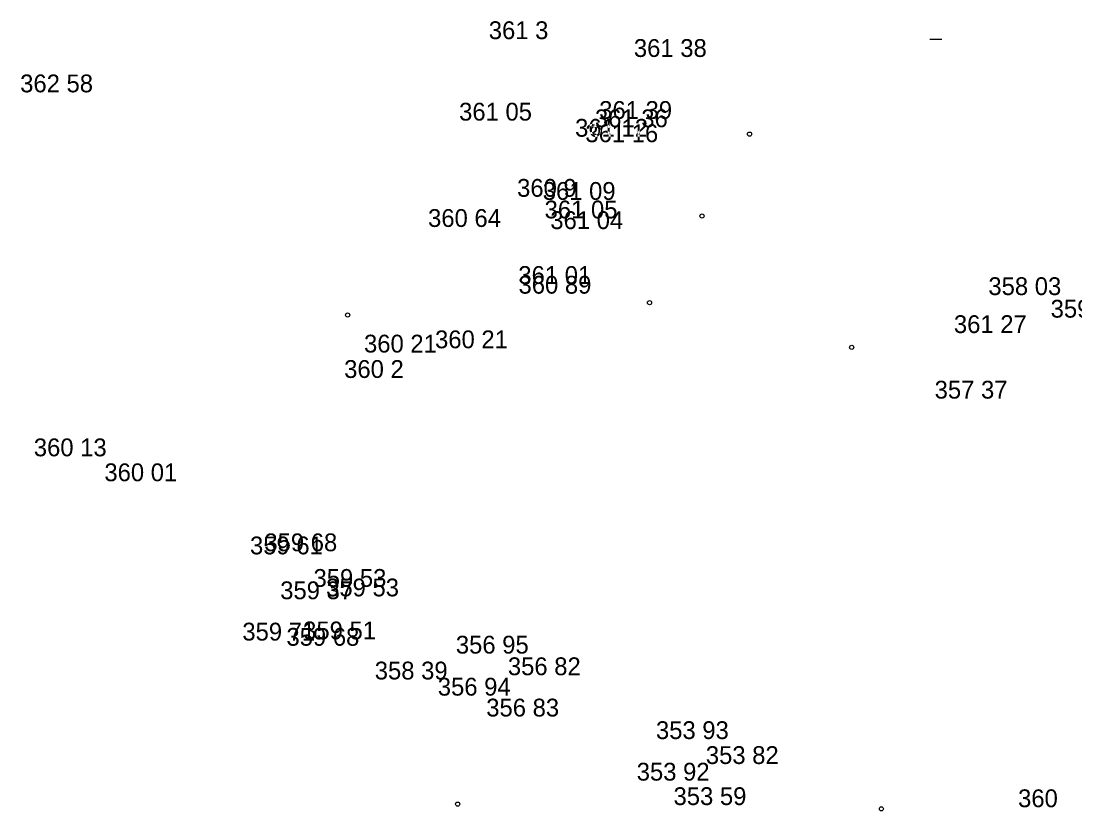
# Model space of a CAD drawing. Extents: x -688316 to -688024, y -973785 to -973591.
# Drawn here: x -688235.96 to -688191.59, y -973732.89 to -973699.62 of the extents above; entities that cross this region are included whole.
import ezdxf

# ---------------------------------------------------------------- set-up
doc = ezdxf.new("R2010")
doc.units = 0
doc.layers.add('Vrstva 3', color=7, linetype='Continuous')
doc.layers.add('Vrstva 58', color=7, linetype='Continuous')

# ---------------------------------------------------------------- blocks, each defined once
blk = doc.blocks.new('B_NESP')
at = {"layer": 'Vrstva 58'}
blk.add_circle((0, 0), 0.875, dxfattribs=at)
blk = doc.blocks.new('B_SPAL')
at = {"layer": 'Vrstva 58'}
blk.add_line((-2.5, 0), (2.5, 0), dxfattribs=at)

msp = doc.modelspace()

# ---------------------------------------------------------------- block references
at = {"layer": 'Vrstva 58', "xscale": 0.1, "yscale": 0.10000000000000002}
for name, p in [('B_SPAL', (-688197.45, -973700.38)), ('B_SPAL', (-688197.45, -973700.38)), ('B_SPAL', (-688197.45, -973700.38)), ('B_SPAL', (-688197.45, -973700.38)), ('B_NESP', (-688205.29, -973704.38)), ('B_NESP', (-688205.29, -973704.38)), ('B_NESP', (-688205.29, -973704.38)), ('B_NESP', (-688205.29, -973704.38)), ('B_NESP', (-688207.29, -973707.83)), ('B_NESP', (-688207.29, -973707.83)), ('B_NESP', (-688207.29, -973707.83)), ('B_NESP', (-688207.29, -973707.83)), ('B_NESP', (-688209.5, -973711.48)), ('B_NESP', (-688209.5, -973711.48)), ('B_NESP', (-688209.5, -973711.48)), ('B_NESP', (-688209.5, -973711.48)), ('B_NESP', (-688222.21, -973712)), ('B_NESP', (-688222.21, -973712)), ('B_NESP', (-688222.21, -973712)), ('B_NESP', (-688222.21, -973712)), ('B_NESP', (-688200.99, -973713.36)), ('B_NESP', (-688200.99, -973713.36)), ('B_NESP', (-688200.99, -973713.36)), ('B_NESP', (-688200.99, -973713.36)), ('B_NESP', (-688217.58, -973732.6)), ('B_NESP', (-688217.58, -973732.6)), ('B_NESP', (-688199.74, -973732.8)), ('B_NESP', (-688199.74, -973732.8))]:
    msp.add_blockref(name, p, dxfattribs=at)

# ---------------------------------------------------------------- texts
at = {"layer": 'Vrstva 3'}
for s, p in [('361 3  ', (-688216.269, -973700.38)), ('361 3  ', (-688216.269, -973700.38)), ('361 3  ', (-688216.269, -973700.38)), ('361 3  ', (-688216.269, -973700.38)), ('361 3  ', (-688216.269, -973700.38)), ('361 3  ', (-688216.269, -973700.38)), ('361 3  ', (-688216.269, -973700.38)), ('361 38 ', (-688210.16, -973701.13)), ('361 38 ', (-688210.16, -973701.13)), ('361 38 ', (-688210.16, -973701.13)), ('361 38 ', (-688210.16, -973701.13)), ('361 38 ', (-688210.16, -973701.13)), ('361 38 ', (-688210.16, -973701.13)), ('361 38 ', (-688210.16, -973701.13)), ('362 58 ', (-688235.996, -973702.62)), ('362 58 ', (-688235.996, -973702.62)), ('362 58 ', (-688235.996, -973702.62)), ('362 58 ', (-688235.996, -973702.62)), ('362 58 ', (-688235.996, -973702.62)), ('362 58 ', (-688235.996, -973702.62)), ('362 58 ', (-688235.996, -973702.62)), ('361 05 ', (-688217.518, -973703.81)), ('361 05 ', (-688217.518, -973703.81)), ('361 05 ', (-688217.518, -973703.81)), ('361 05 ', (-688217.518, -973703.81)), ('361 05 ', (-688217.518, -973703.81)), ('361 05 ', (-688217.518, -973703.81)), ('361 05 ', (-688217.518, -973703.81)), ('361 39 ', (-688211.62, -973703.74)), ('361 39 ', (-688211.62, -973703.74)), ('361 39 ', (-688211.62, -973703.74)), ('361 39 ', (-688211.62, -973703.74)), ('361 39 ', (-688211.62, -973703.74)), ('361 39 ', (-688211.62, -973703.74)), ('361 39 ', (-688211.62, -973703.74)), ('361 36 ', (-688211.8, -973704.09)), ('361 36 ', (-688211.8, -973704.09)), ('361 36 ', (-688211.8, -973704.09)), ('361 36 ', (-688211.8, -973704.09)), ('361 36 ', (-688211.8, -973704.09)), ('361 36 ', (-688211.8, -973704.09)), ('361 36 ', (-688211.8, -973704.09)), ('361 12 ', (-688212.634, -973704.49)), ('361 12 ', (-688212.634, -973704.49)), ('361 12 ', (-688212.634, -973704.49)), ('361 12 ', (-688212.634, -973704.49)), ('361 12 ', (-688212.634, -973704.49)), ('361 12 ', (-688212.634, -973704.49)), ('361 12 ', (-688212.634, -973704.49)), ('361 16 ', (-688212.204, -973704.72)), ('361 16 ', (-688212.204, -973704.72)), ('361 16 ', (-688212.204, -973704.72)), ('361 16 ', (-688212.204, -973704.72)), ('361 16 ', (-688212.204, -973704.72)), ('361 16 ', (-688212.204, -973704.72)), ('361 16 ', (-688212.204, -973704.72)), ('360 9  ', (-688215.077, -973707.02)), ('360 9  ', (-688215.077, -973707.02)), ('360 9  ', (-688215.077, -973707.02)), ('360 9  ', (-688215.077, -973707.02)), ('360 9  ', (-688215.077, -973707.02)), ('360 9  ', (-688215.077, -973707.02)), ('360 9  ', (-688215.077, -973707.02)), ('361 09 ', (-688213.998, -973707.15)), ('361 09 ', (-688213.998, -973707.15)), ('361 09 ', (-688213.998, -973707.15)), ('361 09 ', (-688213.998, -973707.15)), ('361 09 ', (-688213.998, -973707.15)), ('361 09 ', (-688213.998, -973707.15)), ('361 09 ', (-688213.998, -973707.15)), ('361 05 ', (-688213.918, -973707.93)), ('361 05 ', (-688213.918, -973707.93)), ('361 05 ', (-688213.918, -973707.93)), ('361 05 ', (-688213.918, -973707.93)), ('361 05 ', (-688213.918, -973707.93)), ('361 05 ', (-688213.918, -973707.93)), ('361 05 ', (-688213.918, -973707.93)), ('360 64 ', (-688218.825, -973708.29)), ('360 64 ', (-688218.825, -973708.29)), ('360 64 ', (-688218.825, -973708.29)), ('360 64 ', (-688218.825, -973708.29)), ('360 64 ', (-688218.825, -973708.29)), ('360 64 ', (-688218.825, -973708.29)), ('360 64 ', (-688218.825, -973708.29)), ('361 04 ', (-688213.678, -973708.38)), ('361 04 ', (-688213.678, -973708.38)), ('361 04 ', (-688213.678, -973708.38)), ('361 04 ', (-688213.678, -973708.38)), ('361 04 ', (-688213.678, -973708.38)), ('361 04 ', (-688213.678, -973708.38)), ('361 04 ', (-688213.678, -973708.38)), ('361 01 ', (-688215.024, -973710.69)), ('361 01 ', (-688215.024, -973710.69)), ('361 01 ', (-688215.024, -973710.69)), ('361 01 ', (-688215.024, -973710.69)), ('361 01 ', (-688215.024, -973710.69)), ('361 01 ', (-688215.024, -973710.69)), ('361 01 ', (-688215.024, -973710.69)), ('360 89 ', (-688215.016, -973711.1)), ('360 89 ', (-688215.016, -973711.1)), ('360 89 ', (-688215.016, -973711.1)), ('360 89 ', (-688215.016, -973711.1)), ('360 89 ', (-688215.016, -973711.1)), ('360 89 ', (-688215.016, -973711.1)), ('360 89 ', (-688215.016, -973711.1)), ('358 03 ', (-688195.237, -973711.16)), ('358 03 ', (-688195.237, -973711.16)), ('358 03 ', (-688195.237, -973711.16)), ('358 03 ', (-688195.237, -973711.16)), ('358 03 ', (-688195.237, -973711.16)), ('358 03 ', (-688195.237, -973711.16)), ('358 03 ', (-688195.237, -973711.16)), ('359 67 ', (-688192.616, -973712.11)), ('359 67 ', (-688192.616, -973712.11)), ('359 67 ', (-688192.616, -973712.11)), ('359 67 ', (-688192.616, -973712.11)), ('359 67 ', (-688192.616, -973712.11)), ('359 67 ', (-688192.616, -973712.11)), ('359 67 ', (-688192.616, -973712.11)), ('361 27 ', (-688196.688, -973712.76)), ('361 27 ', (-688196.688, -973712.76)), ('361 27 ', (-688196.688, -973712.76)), ('361 27 ', (-688196.688, -973712.76)), ('361 27 ', (-688196.688, -973712.76)), ('361 27 ', (-688196.688, -973712.76)), ('361 27 ', (-688196.688, -973712.76)), ('360 21 ', (-688221.521, -973713.58)), ('360 21 ', (-688221.521, -973713.58)), ('360 21 ', (-688221.521, -973713.58)), ('360 21 ', (-688221.521, -973713.58)), ('360 21 ', (-688221.521, -973713.58)), ('360 21 ', (-688221.521, -973713.58)), ('360 21 ', (-688221.521, -973713.58)), ('360 21 ', (-688218.531, -973713.4)), ('360 21 ', (-688218.531, -973713.4)), ('360 21 ', (-688218.531, -973713.4)), ('360 21 ', (-688218.531, -973713.4)), ('360 21 ', (-688218.531, -973713.4)), ('360 21 ', (-688218.531, -973713.4)), ('360 21 ', (-688218.531, -973713.4)), ('360 2  ', (-688222.357, -973714.65)), ('360 2  ', (-688222.357, -973714.65)), ('360 2  ', (-688222.357, -973714.65)), ('360 2  ', (-688222.357, -973714.65)), ('360 2  ', (-688222.357, -973714.65)), ('360 2  ', (-688222.357, -973714.65)), ('360 2  ', (-688222.357, -973714.65)), ('357 37 ', (-688197.499, -973715.52)), ('357 37 ', (-688197.499, -973715.52)), ('357 37 ', (-688197.499, -973715.52)), ('357 37 ', (-688197.499, -973715.52)), ('357 37 ', (-688197.499, -973715.52)), ('357 37 ', (-688197.499, -973715.52)), ('357 37 ', (-688197.499, -973715.52)), ('360 13 ', (-688235.421, -973717.95)), ('360 13 ', (-688235.421, -973717.95)), ('360 13 ', (-688235.421, -973717.95)), ('360 13 ', (-688235.421, -973717.95)), ('360 13 ', (-688235.421, -973717.95)), ('360 13 ', (-688235.421, -973717.95)), ('360 13 ', (-688235.421, -973717.95)), ('360 01 ', (-688232.451, -973719)), ('360 01 ', (-688232.451, -973719)), ('360 01 ', (-688232.451, -973719)), ('360 01 ', (-688232.451, -973719)), ('360 01 ', (-688232.451, -973719)), ('360 01 ', (-688232.451, -973719)), ('360 01 ', (-688232.451, -973719)), ('359 61 ', (-688226.321, -973722.08)), ('359 61 ', (-688226.321, -973722.08)), ('359 61 ', (-688226.321, -973722.08)), ('359 61 ', (-688226.321, -973722.08)), ('359 61 ', (-688226.321, -973722.08)), ('359 61 ', (-688226.321, -973722.08)), ('359 61 ', (-688226.321, -973722.08)), ('359 68 ', (-688225.716, -973721.95)), ('359 68 ', (-688225.716, -973721.95)), ('359 68 ', (-688225.716, -973721.95)), ('359 68 ', (-688225.716, -973721.95)), ('359 68 ', (-688225.716, -973721.95)), ('359 68 ', (-688225.716, -973721.95)), ('359 68 ', (-688225.716, -973721.95)), ('359 53 ', (-688223.647, -973723.45)), ('359 53 ', (-688223.647, -973723.45)), ('359 53 ', (-688223.647, -973723.45)), ('359 53 ', (-688223.647, -973723.45)), ('359 53 ', (-688223.647, -973723.45)), ('359 53 ', (-688223.647, -973723.45)), ('359 53 ', (-688223.647, -973723.45)), ('359 53 ', (-688223.117, -973723.85)), ('359 53 ', (-688223.117, -973723.85)), ('359 53 ', (-688223.117, -973723.85)), ('359 53 ', (-688223.117, -973723.85)), ('359 53 ', (-688223.117, -973723.85)), ('359 53 ', (-688223.117, -973723.85)), ('359 53 ', (-688223.117, -973723.85)), ('359 37 ', (-688225.049, -973723.97)), ('359 37 ', (-688225.049, -973723.97)), ('359 37 ', (-688225.049, -973723.97)), ('359 37 ', (-688225.049, -973723.97)), ('359 37 ', (-688225.049, -973723.97)), ('359 37 ', (-688225.049, -973723.97)), ('359 37 ', (-688225.049, -973723.97)), ('359 71 ', (-688226.643, -973725.71)), ('359 71 ', (-688226.643, -973725.71)), ('359 71 ', (-688226.643, -973725.71)), ('359 71 ', (-688226.643, -973725.71)), ('359 71 ', (-688226.643, -973725.71)), ('359 71 ', (-688226.643, -973725.71)), ('359 71 ', (-688226.643, -973725.71)), ('359 51 ', (-688224.083, -973725.66)), ('359 51 ', (-688224.083, -973725.66)), ('359 51 ', (-688224.083, -973725.66)), ('359 51 ', (-688224.083, -973725.66)), ('359 51 ', (-688224.083, -973725.66)), ('359 51 ', (-688224.083, -973725.66)), ('359 51 ', (-688224.083, -973725.66)), ('359 68 ', (-688224.786, -973725.93)), ('359 68 ', (-688224.786, -973725.93)), ('359 68 ', (-688224.786, -973725.93)), ('359 68 ', (-688224.786, -973725.93)), ('359 68 ', (-688224.786, -973725.93)), ('359 68 ', (-688224.786, -973725.93)), ('359 68 ', (-688224.786, -973725.93)), ('356 95 ', (-688217.655, -973726.26)), ('356 95 ', (-688217.655, -973726.26)), ('356 95 ', (-688217.655, -973726.26)), ('356 95 ', (-688217.655, -973726.26)), ('356 95 ', (-688217.655, -973726.26)), ('356 95 ', (-688217.655, -973726.26)), ('356 95 ', (-688217.655, -973726.26)), ('358 39 ', (-688221.069, -973727.35)), ('358 39 ', (-688221.069, -973727.35)), ('358 39 ', (-688221.069, -973727.35)), ('358 39 ', (-688221.069, -973727.35)), ('358 39 ', (-688221.069, -973727.35)), ('358 39 ', (-688221.069, -973727.35)), ('358 39 ', (-688221.069, -973727.35)), ('356 82 ', (-688215.465, -973727.17)), ('356 82 ', (-688215.465, -973727.17)), ('356 82 ', (-688215.465, -973727.17)), ('356 82 ', (-688215.465, -973727.17)), ('356 82 ', (-688215.465, -973727.17)), ('356 82 ', (-688215.465, -973727.17)), ('356 82 ', (-688215.465, -973727.17)), ('356 94 ', (-688218.415, -973728.03)), ('356 94 ', (-688218.415, -973728.03)), ('356 94 ', (-688218.415, -973728.03)), ('356 94 ', (-688218.415, -973728.03)), ('356 94 ', (-688218.415, -973728.03)), ('356 94 ', (-688218.415, -973728.03)), ('356 94 ', (-688218.415, -973728.03)), ('356 83 ', (-688216.375, -973728.91)), ('356 83 ', (-688216.375, -973728.91)), ('356 83 ', (-688216.375, -973728.91)), ('356 83 ', (-688216.375, -973728.91)), ('356 83 ', (-688216.375, -973728.91)), ('356 83 ', (-688216.375, -973728.91)), ('356 83 ', (-688216.375, -973728.91)), ('353 93 ', (-688209.231, -973729.86)), ('353 93 ', (-688209.231, -973729.86)), ('353 93 ', (-688209.231, -973729.86)), ('353 93 ', (-688209.231, -973729.86)), ('353 93 ', (-688209.231, -973729.86)), ('353 93 ', (-688209.231, -973729.86)), ('353 93 ', (-688209.231, -973729.86)), ('353 82 ', (-688207.131, -973730.91)), ('353 82 ', (-688207.131, -973730.91)), ('353 82 ', (-688207.131, -973730.91)), ('353 82 ', (-688207.131, -973730.91)), ('353 82 ', (-688207.131, -973730.91)), ('353 82 ', (-688207.131, -973730.91)), ('353 82 ', (-688207.131, -973730.91)), ('353 92 ', (-688210.041, -973731.61)), ('353 92 ', (-688210.041, -973731.61)), ('353 92 ', (-688210.041, -973731.61)), ('353 92 ', (-688210.041, -973731.61)), ('353 92 ', (-688210.041, -973731.61)), ('353 92 ', (-688210.041, -973731.61)), ('353 92 ', (-688210.041, -973731.61)), ('353 59 ', (-688208.491, -973732.64)), ('353 59 ', (-688208.491, -973732.64)), ('353 59 ', (-688208.491, -973732.64)), ('353 59 ', (-688208.491, -973732.64)), ('353 59 ', (-688208.491, -973732.64)), ('353 59 ', (-688208.491, -973732.64)), ('353 59 ', (-688208.491, -973732.64)), ('360    ', (-688193.987, -973732.73)), ('360    ', (-688193.987, -973732.73)), ('360    ', (-688193.987, -973732.73)), ('360    ', (-688193.987, -973732.73)), ('360    ', (-688193.987, -973732.73)), ('360    ', (-688193.987, -973732.73)), ('360    ', (-688193.987, -973732.73))]:
    msp.add_text(s, height=0.75, dxfattribs=at).set_placement(p)

doc.saveas('drawing.dxf')
